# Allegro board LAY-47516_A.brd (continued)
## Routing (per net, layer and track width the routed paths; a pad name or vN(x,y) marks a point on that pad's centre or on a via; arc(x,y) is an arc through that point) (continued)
VCC_2V0: length 7.6
  TOP w0.254: 22.35,73.59 TP13.1 ; TP13.1 21.9,74.04 ; TP13.1 22.8,74.04 ; TP13.1 22.35,74.49 ; 17.59,74.81 C12.1 ; C12.1 18.03,74.39 ; C12.1 18.48,74.81 ; U4.2 17.27,73.78
  BOTTOM w0.254: JP1.3 16.08,60.62 ; JP1.3 17.03,59.66 ; JP1.3 15.12,59.66 ; JP1.3 16.08,58.71
  vias: v2(17.53,72.52) v2(18.67,73.53) v2(18.67,72.52) v2(19.81,75.56) v2(19.81,74.55) v2(19.81,73.53) v2(19.81,72.52) v2(20.95,75.56) v2(20.95,74.55) v2(20.95,73.53) v2(20.95,72.52) v2(22.1,75.56)
VCC_3V3: length 39.7
  TOP w0.254: C27.1 99.44,70.28 99.05,69.89 U12.14 ; C27.1 100.17,71.79 v2(100.2,71.75) ; C27.1 98.46,71.79 C28.1 ; U11.2 v2(24.46,23.06) ; U11.1 v2(23.49,22.3) ; R20.1 v2(25.81,19.8)
  TOP w0.381: 22.35,68.64 TP12.1 ; TP12.1 22.8,69.09 ; TP12.1 22.35,69.54 ; TP12.1 21.9,69.09 ; 17.43,67.61 C7.1 17.01,68.11 ; 17.06,68.68 U3.4 17.7,69.1 ; U3.5 17.7,70.05
  TOP w0.508: R158.1 27.49,36.95 v2(27.3,36.95) ; R153.1 v2(77.14,22.66) ; C22.1 v2(24.46,22.28) ; R152.1 v2(13.97,27.99) ; R37.1 v2(92.09,83.95) 93.12,84.97 93.12,86.31 93.95,87.14 D4.2
  L3_PWR_1 w0.254: JP1.1 17.03,64.74 ; JP1.1 16.08,63.79 ; JP1.1 15.12,64.74 ; JP1.1 16.08,65.7
  BOTTOM w0.508: v2(27.3,36.95) 27.07,36.71 27.07,26.89 v2(26.44,26.26) ; v2(24.46,23.06) v2(24.46,22.28)
  vias: v2(18.52,70.48) v2(18.54,68.96) v2(18.54,67.44) v2(19.69,69.34) v2(19.81,70.48) v2(19.81,67.44) v2(20.45,68.33) v2(21.08,70.48) v2(21.08,69.34) v2(21.08,67.44) v2(22.35,70.48) v2(22.35,67.44)
VCC_3V3_2V0: length 83.1
  TOP w0.165: R62.1 v2(41.24,40.64) ; R34.1 v2(102.11,58.84) ; R149.1 v2(18.26,49.91) ; R148.1 v2(14.91,49.91) ; R35.1 v2(103,58.84)
  TOP w0.254: v2(101.76,72.77) R33.1 R32.1 ; U18.14 44.57,77.52 44.67,77.62 45.35,77.62 v2(45.88,77.09) ; U12.1 96.47,68.31 95.63,69.15 C29.1 v2(96.39,71.75) ; v2(25.71,49.57) 25.52,49.38 U22.16 ; U11.16 22.99,22.61 22.83,22.45 C24.1 ; 17.4,84.59 C466.1 v1(18.29,82.95) ; C97.1 19.88,13.46 19.74,13.59 U24.16 ; U26.1 C444.1 40.92,97.17 40.78,97.03 v2(40.77,97.03)
  TOP w0.381: C8.1 JS1.1
  TOP w0.508: v2(49.34,96.54) R19.1 ; v2(40.78,92.09) C442.1 U25.1 ; D9.A v2(45.52,86.33) ; v2(10.29,7.75) 10.67,8.13 C95.1 11.56,6.57 11.52,6.54 J18.11 ; C84.1 v2(45.88,77.09) ; C58.1 v2(80.64,45.31) ; R44.1 v2(95.48,35.24) ; R61.2 v2(81.66,45.31) ; R117.2 v2(39.34,76.2) ; v2(23.62,21.08) 23.22,21.49 C24.1 ; C59.1 37.91,35.43 37.78,35.56 J10.11 ; R43.1 v2(95.48,13.08) ; v2(46.61,46.86) 47.65,46.86 ; C93.1 26.07,49.93 v2(25.71,49.57) ; C97.1 v2(21.84,13.46) ; R147.1 v2(95.48,46.35) ; R45.1 v2(95.35,24.2) ; R42.2 v2(95.27,89.41)
  L3_PWR_1 w0.254: 35.58,35.56 J10.11 ; J10.11 37.62,35.56 ; J10.11 36.6,36.58 ; 15.12,62.2 JP1.2 ; JP1.2 16.08,61.25 ; JP1.2 17.03,62.2 ; 10.51,5.33 J18.11 ; J18.11 12.54,5.33 ; J18.11 11.52,4.31 ; J18.11 11.52,6.35 ; JP21.1 42.1,55.37 ; JP21.1 41.15,54.42 ; JP21.1 41.15,56.33 ; JP21.1 40.19,55.37 ; 21.97,60.77 JS1.1 21.02,61.72 ; JP20.1 82.74,57.53 ; JP20.1 81.79,58.49 ; JP20.1 80.83,57.53 ; JP20.1 81.79,56.58 ; J18.12 11.52,3.81 ; J18.12 12.54,2.79 ; J18.12 10.51,2.79 ; J18.12 11.52,1.77 ; JP22.1 93.44,34.54 ; JP22.1 92.48,33.59 ; JP22.1 92.48,35.5 ; JP22.1 91.53,34.54 ; JP8.1 41.39,87.33 ; JP8.1 40.44,88.28 ; JP8.1 39.48,87.33 ; JP8.1 40.44,86.37
  BOTTOM w0.165: v1(56.9,31.37) 56.87,31.4 R75.1 ; v1(49.53,49.78) 49.16,49.41 R65.1
VCC_IF_LINK: length 37.6
  TOP w0.254: v2(32,77.6) 30.71,77.6 30.2,77.09 C91.1 29.54,75.34 U21.6 ; U20.6 29.36,82.17 C87.1 30.12,83.57 30.63,84.07 v2(31.24,84.07) ; U17.8 38.75,64.65 38.73,64.64 C83.1 37.46,65.28 37,65.74 v2(36.58,65.74) ; U19.6 29.76,87.67 C86.1 30.18,88.65 30.68,89.15 v2(32,89.15)
  TOP w0.508: C89.1 51.21,73.88 J17.1 ; R122.1 v2(31.99,80.59) ; R126.1 v2(32.04,73.6) ; R116.1 v2(32.03,86.03)
  L3_PWR_1 w0.203: J17.1 50.29,73.02 v2(39.12,73.02)
  BOTTOM w0.254: JP8.2 40.44,85.74 ; JP8.2 41.39,84.79 ; JP8.2 39.48,84.79 ; JP8.2 40.44,83.83
ACC_FC0_I2C_SCL: length 64.9
  TOP w0.165: U12.4 88.32,66.81 86.64,65.13 49.66,65.13 v1(46.63,62.1) ; R77.2 v1(46.63,50.67)
  BOTTOM w0.165: v1(46.63,50.67) v1(46.63,62.1)
ACC_FC0_I2C_SDA: length 72.2
  TOP w0.165: v1(57.25,64.64) 97.41,64.64 98.05,65.29 U12.6
  BOTTOM w0.165: R84.2 57.15,35.44 57.15,50.8 58.17,51.82 58.17,54.86 57.25,55.78 v1(57.25,64.64)
ACC_INT_EXP_P1_23: length 115.5
  TOP w0.165: v1(73.15,74.17) 73.28,74.04 99.06,74.04 99.19,74.17 99.69,74.17 99.95,73.91 99.95,73.74 101.22,72.47 101.22,72.01 101.47,71.75 R36.1 ; v1(73.15,48.51) 86.13,48.51 J9.5 ; v1(73.15,28.83) v1(62.48,28.83) ; v1(62.48,39.24) 61.19,40.54 J32.27
  BOTTOM w0.165: v1(73.15,74.17) v1(73.15,48.51) v1(73.15,28.83) ; v1(62.48,39.24) v1(62.48,28.83)
ARD_ADC0_0_P: length 133.5
  TOP w0.14: J12.10 81.03,15.24 80.64,14.86 76.83,14.86 76.2,15.49 71.37,15.49 71.12,15.24 v1(65.28,15.24) ; v1(50.29,46.73) 50.54,46.48 52.83,46.48 53.19,46.13 U28.12 J32.12 ; v1(47.27,20.4) 47.02,20.14 47.02,18.31 46.61,17.91 42.67,17.91 41.66,18.92 37.74,18.92 J13.3 ; JP4.3 30.35,12.7 J13.8 35.31,11.45 35.31,6.35 37.46,4.19 v1(65.28,4.19)
  BOTTOM w0.14: JP4.3 32.13,11.68 32.38,11.43 34.67,11.43 35.31,12.07 35.31,15.49 36.6,16.79 J13.3 ; v1(65.28,4.19) v1(65.28,15.24) ; v1(50.29,46.73) 48.8,46.73 46.75,44.68 46.75,20.91 v1(47.27,20.4)
ARD_BTN_USR_P1_9: length 177.8
  TOP w0.165: v1(38.73,2.54) 39.88,1.4 85.47,1.4 86.11,2.03 86.11,2.79 87,3.68 88.52,3.68 90.93,1.27 v1(94.49,1.27) ; v1(96.27,51.18) 80.01,51.18 78.87,52.32 64.39,52.32 62.69,50.63 J32.3 ; R47.2 v1(96.27,21.08)
  BOTTOM w0.165: v1(38.73,2.54) 38.73,20.6 37.49,21.84 35.58,21.84 J13.2 ; v1(94.49,1.27) 94.87,1.65 94.87,17.4 96.27,18.8 v1(96.27,21.08) 96.52,21.34 96.52,50.93 v1(96.27,51.18)
ARD_CMP0_IN_A: length 144.6
  TOP w0.165: v1(77.47,58.93) 83.26,58.93 87.4,54.79 J9.1 ; v1(78.49,4.32) 66.17,4.32 65.79,4.7 44.6,4.7 J13.7 ; J32.36 U28.36 v1(78.11,45.63) ; J11.2 91.06,14.48 88.01,11.43 86.87,11.43 86.11,12.19 86.11,13.46 85.6,13.97 78.6,13.97 v1(78.49,14.08)
  BOTTOM w0.165: v1(77.47,58.93) 77.47,46.26 v1(78.11,45.63) 78.16,45.58 78.16,14.41 v1(78.49,14.08) v1(78.49,4.32)
ARD_INT_P0_15: length 64.3
  TOP w0.165: v1(54.99,13.97) 70.31,13.97 71.45,15.11 76.15,15.11 78.56,12.7 J12.12 ; v1(54.86,43.43) 55.46,43.43 55.63,43.6 55.63,44.83 55.33,45.13 J32.14
  BOTTOM w0.165: v1(54.99,13.97) 54.99,43.31 v1(54.86,43.43)
ARD_LEDB_PWM: length 119.6
  TOP w0.165: v1(62.69,61.72) 96.24,61.72 v1(96.75,61.21) ; J32.51 U28.51 v1(62.69,55.75) ; v1(98.88,74.55) 98.12,74.55 97.87,74.8 R161.1 ; J12.8 86.13,16.51 88.77,16.51 90.55,18.29 95.12,18.29 95.89,17.53 v1(99.44,17.53)
  BOTTOM w0.165: v1(98.88,74.55) 98.88,71.86 96.75,69.73 v1(96.75,61.21) 96.75,55.88 99.44,53.19 v1(99.44,17.53) ; v1(62.69,55.75) v1(62.69,61.72)
ARD_LEDG_PWM: length 106.7
  TOP w0.165: v1(98.51,81.97) 98.5,81.96 R162.1 ; J12.4 86.13,21.59 93.98,21.59 94.56,22.17 v1(94.56,24) ; v1(91.92,43.56) 79.88,43.56 79.5,43.94 79.5,46.1 78.97,46.63 U28.38 J32.38
  BOTTOM w0.165: v1(98.51,81.97) 93.75,81.97 91.92,80.14 v1(91.92,43.56) 91.92,41.83 94.74,39.01 94.74,25.27 94.56,25.1 v1(94.56,24)
ARD_LEDR_PWM: length 122
  TOP w0.165: J9.2 83.57,52.32 83.06,52.83 67.06,52.83 65.02,54.86 64.01,54.86 63.69,54.55 U28.49 J32.49 ; v1(94.11,20.32) J12.5 ; J9.13 v1(94.11,37.08) ; v1(88.54,88.65) R164.1
  BOTTOM w0.165: v1(88.54,88.65) 83.82,83.92 83.82,53.34 84.84,52.32 J9.2 84.86,54.76 85.85,55.75 90.68,55.75 91.44,54.99 91.44,41.5 94.11,38.84 v1(94.11,37.08) v1(94.11,20.32)
ARD_MIK_ADC0_8_N: length 108.5
  TOP w0.14: J7.1 62.85,6.39 61.65,5.18 48.03,5.18 47.09,6.12 v1(47.09,10.54) ; J32.7 U28.7 51.42,48.63 50.55,47.75 v1(50.29,47.75) ; v1(47.09,17.2) 46.53,16.64 35.99,16.64 35.48,17.14 35.48,19.2 J13.1 37.62,19.3 37.62,19.3 37.72,19.2 41.77,19.2 42.79,18.19 46.49,18.19 46.74,18.43 46.74,20.18 v1(46.47,20.45)
  BOTTOM w0.14: J13.1 35.34,19.06 33.15,19.06 30.86,16.76 JP4.1 ; v1(50.29,47.75) 49.55,47.01 48.69,47.01 46.45,44.77 46.45,44.7 46.47,44.67 v1(46.47,20.45) ; v1(47.09,10.54) v1(47.09,17.2)
ARD_MIK_FC0_I2C_SCL: length 34.6
  TOP w0.165: v1(45.72,48.77) 45.75,48.79 R80.2
  BOTTOM w0.165: v1(45.72,48.77) 45.72,20.12 J8.5
ARD_MIK_FC0_I2C_SDA: length 21.4
  TOP w0.165: J8.6 56.99,19.09 v1(57.02,19.05)
  BOTTOM w0.165: v1(57.02,19.05) 56.77,19.3 56.77,30.23 57.73,31.19 R88.2
ARD_MIK_FC1_USART_RXD: length 102.7
  TOP w0.165: v1(61.34,37.46) 60.19,38.62 J32.25 ; v1(64.26,5.59) 70.48,5.59 71.02,5.05 75.21,5.05 77.77,7.62 J12.16 ; v1(64.26,12.04) v1(61.34,12.04) 57.51,12.04 56.93,11.47 J8.3 ; J13.4 35.48,16.36 46.91,16.36 48.33,17.77 61.33,17.77 v1(61.34,17.78)
  BOTTOM w0.165: v1(61.34,12.04) v1(61.34,17.78) v1(61.34,37.46) ; v1(64.26,12.04) v1(64.26,5.59)
ARD_MIK_FC1_USART_TXD: length 94.5
  TOP w0.165: J32.62 57.19,52.28 v1(57.53,51.94) ; J12.14 70.36,10.16 67.82,12.7 v1(56.52,12.7) 50.6,12.7 J8.4 35.3,14.01 J13.6
  BOTTOM w0.165: v1(57.53,51.94) 57.53,51.82 56.64,50.93 56.64,35.81 56.26,35.43 56.26,18.92 56.52,18.67 v1(56.52,12.7)
ARD_MIK_HSSPI_MISO: length 105.9
  TOP w0.165: J9.12 80.39,39.62 v1(80.14,39.88) ; v1(80.44,15.34) 77.27,15.34 76.06,16.55 J7.5
  BOTTOM w0.165: JP25.1 72.64,97.25 78.23,91.66 78.23,47.37 80.14,45.47 v1(80.14,39.88) 80.44,39.57 v1(80.44,15.34)
ARD_MIK_HSSPI_MOSI: length 123.7
  TOP w0.165: v1(20.83,19.69) 22.48,19.69 23.11,19.05 29.34,19.05 34.1,23.81 40.57,23.81 43.69,26.92 50.67,26.92 52.7,24.89 v2(70.48,24.89) ; v1(71.63,37.08) J9.14 ; U24.11 16.52,11.57 16.38,11.43 v1(16.38,10.67) ; v1(70.48,19.09) J7.6 ; R138.1 v1(21.69,9.96) ; J32.40 U28.40 v1(71.63,47.63)
  BOTTOM w0.165: v1(71.63,47.63) v1(71.63,37.08) 71.63,26.67 70.48,25.53 v2(70.48,24.89) v1(70.48,19.09) ; v1(21.69,9.96) 21.15,10.5 20.28,10.5 19.81,10.03 18.54,10.03 17.91,10.67 v1(16.38,10.67) 16.38,12.83 19.81,16.26 19.81,18.67 v1(20.83,19.69)
ARD_MIK_HSSPI_SCK: length 105.8
  TOP w0.165: v1(76.71,42.16) J9.10 ; v1(76.07,14.01) J7.4
  BOTTOM w0.165: v1(76.07,14.01) 76.07,22.48 76.71,23.11 v1(76.71,42.16) 76.71,89.59 69.34,96.96 JP26.1
ARD_MIK_HSSPI_SSEL1: length 125.8
  TOP w0.165: v1(70.87,34.54) J9.16 ; U24.14 18.02,12.03 18.75,11.3 v1(21.72,11.3) ; J7.3 v1(69.85,11.47) ; v1(21.97,17.78) 29.72,17.78 34.67,22.73 41.02,22.73 44.13,25.85 50.23,25.85 52.83,23.24 v2(69.85,23.24) ; v1(70.87,47.12) 70.85,47.13 U28.39 J32.39 ; v1(24.26,10.03) R139.1
  BOTTOM w0.165: v1(21.97,17.78) 21.21,17.02 21.21,11.81 v1(21.72,11.3) 21.72,10.92 22.61,10.03 v1(24.26,10.03) ; v1(70.87,47.12) v1(70.87,34.54) 70.87,26.92 69.85,25.91 v2(69.85,23.24) v1(69.85,11.47)
ARD_MIK_P1_5: length 75.3
  TOP w0.165: J32.22 U28.22 v1(58.69,40.64) ; v1(59.82,6.39) J8.1
  BOTTOM w0.165: v1(58.69,40.64) 58.69,36.05 59.82,34.92 v1(59.82,6.39) 59.82,3.43 60.58,2.67 84.73,2.67 J12.20
BRG_I2C0_SCL: length 19.5
  TOP w0.102: U16.D6 v1(11.84,38.17)
  TOP w0.165: R91.2 v1(10.62,43.31)
  BOTTOM w0.165: JS4.1 11.43,53.26 11.43,46.35 11.3,46.23 11.3,45.47 10.62,44.78 v1(10.62,43.31) 11.84,42.09 v1(11.84,38.17)
BRG_I2C0_SDA: length 20.3
  TOP w0.102: U16.E6 v1(12.64,38.17)
  TOP w0.165: R92.2 v1(11.84,43.31)
  BOTTOM w0.165: JS5.1 14.55,53.04 14.55,52.45 12.19,50.09 12.19,46.35 12.32,46.23 12.32,45.34 11.84,44.86 v1(11.84,43.31) 12.19,42.95 12.19,38.61 v1(12.64,38.17)
BRG_INTR_ISP: length 15.6
  TOP w0.102: U16.J5 16.65,36.55 17.3,36.55
  TOP w0.165: 17.3,36.55 18.01,36.55 18.53,37.07 v1(21.97,37.07) ; R132.2 v1(20.88,45.11)
  BOTTOM w0.165: v1(20.88,45.11) 22.1,43.89 22.1,37.2 v1(21.97,37.07)
BRG_INTR_ISP_DIR: length 12.9
  TOP w0.102: 17.26,38.98 16.65,38.98 U16.J7
  TOP w0.165: 17.26,38.98 18.54,40.26 18.54,41.66 20.29,43.41 v1(21.57,43.41) R134.1 U22.7
BRG_ISP_CTRL: length 20.8
  TOP w0.102: U16.A9 v1(8.57,40.17)
  TOP w0.165: v1(18.29,38.76) 19.25,38.76 19.35,38.66 23.31,38.66 24.53,39.88 25.22,39.88 25.46,39.64 U23.2
  BOTTOM w0.165: v1(18.29,38.76) 17.17,37.64 11.1,37.64 v1(8.57,40.17)
BRG_RESET_TXEN: length 48.9
  TOP w0.102: 15.04,41.2 15.04,40.57 U16.G9
  TOP w0.165: R128.1 29.42,74.64 v1(29.4,74.66) 29.37,74.69 U21.5 ; 15.04,41.2 15.04,43.87 v1(17.51,46.34)
  BOTTOM w0.165: v1(17.51,46.34) 17.51,47.73 20.95,51.18 28.7,51.18 31.24,53.72 31.24,57.66 28.7,60.2 28.7,73.96 v1(29.4,74.66)
BRG_SPI1_MISO: length 22.6
  TOP w0.165: U16.J1 17.62,32.38 18.54,32.38 20.7,30.23 20.7,27.94 18.13,25.37 18.13,18.64 17.02,17.53 U24.5
BRG_SPI1_MOSI: length 23.8
  TOP w0.102: U16.J2 15.84,34.17 15.84,33.31
  TOP w0.165: U24.6 16.52,15.66 16.49,15.69 16.49,17.63 17.83,18.97 17.83,25.22 17.78,25.27 17.78,25.53 20.32,28.07 20.32,29.97 18.29,32 17.14,32 15.84,33.31
BRG_SPI1_SCLK: length 33.5
  TOP w0.165: U24.4 17.52,15.66 17.53,15.66 17.53,16.64 v1(17.78,16.89) ; v1(18.36,42.98) 17.58,42.2 17.58,40.72 U16.K9
  BOTTOM w0.165: v1(18.36,42.98) 19.84,41.5 19.84,35.99 20.57,35.26 20.57,27.05 17.78,24.26 v1(17.78,16.89)
BRG_SPI1_SSEL: length 35
  TOP w0.165: U16.K10 17.04,42.56 v1(18.57,44.09) ; U24.3 18.02,15.99 v1(18.41,16.38)
  BOTTOM w0.165: v1(18.41,16.38) 18.92,16.89 18.92,24.89 20.95,26.92 20.95,35.48 20.27,36.17 20.27,42.39 v1(18.57,44.09)
BRG_TCK_SWCLK: length 38.9
  TOP w0.165: v1(38.93,52.26) 38.61,51.94 22.4,51.94 18.52,48.06 18.52,46.61 15.88,43.97 15.88,41.41 U16.H10 ; U17.2 v1(39.68,59.41)
  BOTTOM w0.165: v1(39.68,59.41) 38.93,58.66 v1(38.93,52.26)
BRG_TDI: length 39.1
  TOP w0.165: U17.3 v1(40.33,58.97) ; U16.J10 16.24,43.74 18.93,46.44 18.93,47.89 22.61,51.56 v1(39.37,51.56)
  BOTTOM w0.165: v1(40.33,58.97) 39.37,58.01 v1(39.37,51.56)
BRG_TDO_SWO: length 60.7
  TOP w0.102: 17.27,39.78 16.64,39.78 U16.J8
  TOP w0.165: 17.27,39.78 17.91,40.41 17.91,41.66 19.41,43.15 19.41,47.6 v1(21.17,49.36) ; U19.3 27.01,86.37 27.52,85.86 27.52,72.81 28.87,71.46 v1(29.21,71.46)
  BOTTOM w0.165: v1(21.17,49.36) 21.17,50.41 21.49,50.72 28.88,50.72 31.62,53.47 31.62,57.91 29.21,60.32 v1(29.21,71.46)
BRG_TMS_SWDIO: length 62.5
  TOP w0.165: U16.K4 18.26,36.17 18.72,36.63 23.32,36.63 24.67,37.97 27.18,37.97 27.89,38.68 v1(29.46,38.68) ; U20.3 26.42,79.02 27.18,78.26 27.18,72.52 28.91,70.78 31.45,70.78 v1(31.62,70.61)
  BOTTOM w0.165: v1(29.46,38.68) 29.46,39.24 32.13,41.91 32.13,50.55 34.42,52.83 34.42,65.28 31.62,68.07 v1(31.62,70.61)
BRG_TMS_SWDIO_TXEN: length 66.8
  TOP w0.102: U16.J4 16.64,35.76 18.36,35.76
  TOP w0.165: v1(32.73,70.88) 31.67,71.94 29.02,71.94 27.89,73.08 27.89,81.37 28.03,81.52 U20.5 29.62,81.52 29.64,81.55 R124.1 ; 18.36,35.76 18.92,36.32 23.49,36.32 24.77,37.59 27.3,37.59 27.94,38.23 29.84,38.23 v1(30.23,38.61)
  BOTTOM w0.165: v1(32.73,70.88) 32.73,68.49 34.92,66.29 34.92,52.58 32.51,50.16 32.51,41.27 30.28,39.04 30.28,38.66 v1(30.23,38.61)
BRG_TRST_SWDRST: length 40.2
  TOP w0.165: U21.3 25.02,74.04 v1(22.48,71.5) ; U16.D10 12.24,41.93 v1(12.8,42.49)
  BOTTOM w0.165: v1(22.48,71.5) 22.99,70.99 22.99,56.39 13.82,47.22 13.82,45.59 12.8,44.58 v1(12.8,42.49)
BRG_UART0_RXD: length 13.3
  TOP w0.165: U22.3 v1(23.18,47.66) ; v1(14.45,41.83) 14.64,41.65 U16.G10
  BOTTOM w0.165: v1(23.18,47.66) 23.18,47 22.78,46.61 20.42,46.61 15.65,41.83 v1(14.45,41.83)
BRG_UART0_TXD: length 17.5
  TOP w0.102: U16.G7 v1(14.23,38.97)
  TOP w0.165: U22.4 23.46,47.16 23.45,47.17 v1(22.63,47.17) R129.2
  BOTTOM w0.165: v1(14.23,38.97) 13.67,38.97 13.44,39.2 13.44,41.5 14.35,42.42 15.54,42.42 20.29,47.17 v1(22.63,47.17)
CAN__HSSPI_ISP_PIO1_2: length 150.2
  TOP w0.165: U24.13 v1(17.52,11.75) 17.52,10.84 16.61,9.93 R143.1 ; v2(65.66,23.79) 52.79,23.79 50.38,26.21 43.99,26.21 40.87,23.09 34.52,23.09 29.59,18.16 22.48,18.16 22.23,18.41 v1(21.59,18.41) ; v1(67.69,48.13) U28.41 J32.41 ; JP26.2 70.61,105.66 70.61,90.93 v1(67.56,87.88)
  BOTTOM w0.165: v1(67.56,87.88) 67.56,64.14 65.79,62.36 65.79,53.21 67.69,51.31 v1(67.69,48.13) 67.69,45.59 65.66,43.56 v2(65.66,23.79) ; v1(17.52,11.75) 20.83,15.05 20.83,17.65 v1(21.59,18.41)
CAN__HSSPI_ISP_PIO1_3: length 154
  TOP w0.165: v1(68.33,48.64) 68.31,48.63 U28.42 J32.42 ; JP25.2 71.37,105.66 71.37,90.68 v1(68.07,87.38) ; R140.1 v1(19.15,10.63) ; U24.12 17.02,11.62 17.02,11.62 v1(17.02,11.24) ; v2(66.17,24.38) 52.7,24.38 50.52,26.56 43.84,26.56 40.72,23.45 34.37,23.45 29.46,18.54 22.61,18.54 22.1,19.05 v1(21.21,19.05)
  BOTTOM w0.165: v1(68.07,87.38) 67.95,87.25 67.95,63.75 66.17,61.98 66.17,53.34 68.33,51.18 v1(68.33,48.64) 68.33,45.47 66.17,43.31 v2(66.17,24.38) ; v1(21.21,19.05) 20.32,18.16 20.32,15.24 17.02,11.94 v1(17.02,11.24) 18.55,11.24 v1(19.15,10.63)
CAN_RXD: length 53.3
  TOP w0.165: U25.3 43.11,89.1 43.69,88.52 66.17,88.52 67.56,89.92 67.56,97.03 65.53,99.06 65.53,107.44 66.29,108.2 71.37,108.2 JP25.3
CAN_TXD: length 54.6
  TOP w0.165: JP26.3 68.33,110.49 66.42,110.49 65.02,109.09 65.02,99.06 67.18,96.9 67.18,90.07 66.14,89.03 51.05,89.03 50.06,90.02 50.06,90.7 49.35,91.41 47.04,91.41 46.61,91.84 46.61,93.86 46.04,94.42 43.75,94.42 43.24,94.94 U26.3
CANH: length 31.1
  TOP w0.165: J19.7 44.26,101.19 45.63,99.82 57.75,99.82 D3.1 60.53,95.32 JP23.2 58.55,93.34 U9.7
CANL: length 33.3
  TOP w0.165: J19.2 45.64,100.66 46.1,100.2 58.93,100.2 61.34,97.79 61.66,97.79 D3.2 62.41,96.06 62.1,95.76 61.59,95.76 60.71,94.87 60.71,94.11 59.44,92.84 JP24.2 58.42,92.07 U9.6
EXP_CMP0_IN_B: length 103.3
  TOP w0.165: v1(78.74,46.13) U28.37 J32.37 ; J11.1 91.44,17.02 88.52,14.1 86.61,14.1 86.11,14.61 86.11,15.75 85.34,16.51 80.33,16.51 v1(79.72,17.12) 79.19,17.65 71.63,17.65 70.61,16.64 57.4,16.64 56.13,15.37 36.73,15.37 J13.5
  BOTTOM w0.165: v1(79.72,17.12) 78.74,18.1 v1(78.74,46.13)
EXP_CMP0_OUT: length 124.4
  TOP w0.165: J11.3 91.57,11.94 88.44,8.81 76.99,8.81 75.67,7.49 70.71,7.49 69.19,9.02 v1(55.5,9.02) ; J32.2 v1(55.63,51.13)
  BOTTOM w0.165: v1(55.63,51.13) 55.63,35.81 55.5,35.69 v1(55.5,9.02) ; J11.3 90.37,14.53 90.37,48.31 88.9,49.78 J9.3
EXP_ISP_P1_29: length 133.4
  TOP w0.165: v1(63.37,52.07) 62.03,52.07 61.69,52.41 J32.53 ; v1(40.08,11.05) 47.65,11.05 48.67,10.03 v1(63.75,10.03) 69.01,10.03 71.2,7.85 75.26,7.85 76.68,9.27 v1(82.42,9.27) ; R137.2 v1(25.21,11.94)
  BOTTOM w0.165: v1(63.75,10.03) 63.75,12.19 64.01,12.45 64.01,48.51 63.5,49.02 63.5,51.94 v1(63.37,52.07) ; v1(82.42,9.27) 83.57,9.27 83.82,9.02 85.6,9.02 86.11,9.53 86.11,11.41 J12.11 ; v1(25.21,11.94) 27.05,13.78 27.05,17.91 28.4,19.26 29.93,19.26 33.02,22.35 33.02,24.36 J10.20 36.98,22.48 37.46,22.48 40.08,19.86 v1(40.08,11.05)
FB: length 20.5
  TOP w0.165: C461.1 L11.2 61.76,32.31 61.76,32.31 C18.1 60.56,32.31 60.32,32.54 60.32,33.81 59.92,34.21 C19.1 59.28,37.57 59.69,37.97 U28.24 J32.24 59.69,43.69 60.07,44.07 61.85,44.07 62.19,43.73 J32.29
FC0_I2C_SCL: length 46.8
  TOP w0.165: v1(62.19,61.21) 48.92,61.21 v1(47.65,59.94) ; J32.52 v1(62.19,55.12) ; v1(47.65,51.05) R77.1 R80.1 R74.2 47.14,47.37 40.26,47.37 38.61,45.72 J10.3
  BOTTOM w0.165: v1(62.19,55.12) v1(62.19,61.21) ; v1(47.65,59.94) v1(47.65,51.05)
FC0_I2C_SDA: length 63.6
  TOP w0.165: v1(75.69,50.16) 75.66,50.13 U28.45 J32.45 ; J9.18 77.47,32 v1(75.68,30.22) 75.44,29.97 v1(57.91,29.97)
  BOTTOM w0.165: v1(75.69,50.16) 75.69,30.23 v1(75.68,30.22) ; v1(57.91,29.97) 57.91,30.61 58.29,30.99 58.29,33.02 58.14,33.17 R88.1 R75.2 R84.1
FC0_USART_RXD: length 66.5
  TOP w0.165: J32.61 U28.61 57.69,54.86 57.31,55.24 54.36,55.24 53.59,54.48 45.97,54.48 42.42,50.93 30.35,50.93 29.08,49.66 v1(29.08,49.15) 29.46,49.15 29.67,48.95 R130.2 ; 20.4,22.73 v1(19.43,22.73)
  BOTTOM w0.165: v1(19.43,22.73) 19.43,24.38 21.34,26.29 21.34,35.18 22.48,36.32 22.48,44.2 27.43,49.15 v1(29.08,49.15)
FC0_USART_TXD: length 91.8
  TOP w0.165: v1(21.07,25.34) 20.7,25.71 R26.2 ; v1(42.67,28.58) 42.24,29.01 35.13,29.01 J10.18 ; J32.63 56.69,52.63 56.52,52.45 45.59,52.45 43.56,50.42 v1(42.67,50.42) 31.5,50.42 v1(30.23,49.15) 30.23,47.37 30.02,47.16 R131.2
  BOTTOM w0.165: v1(30.23,49.15) 28.24,47.16 26.34,47.16 22.86,43.69 22.86,36.2 21.84,35.18 21.84,26.12 v1(21.07,25.34) ; v1(42.67,28.58) v1(42.67,50.42)
FC1_I2C_SCL: length 225.7
  TOP w0.165: v1(64.26,64.14) 49.53,64.14 43.74,58.34 40.31,58.34 35.42,53.45 14.16,53.45 JS4.2 R148.2 1.78,49.91 1.75,49.93 v1(1.37,49.93) ; J12.19 85.88,1.02 36.07,1.02 v1(35.05,2.03) ; v1(17.91,9.93) R144.2 17.3,8.54 v1(17.3,6.7) ; J32.47 v1(64.26,51.13)
  BOTTOM w0.165: v1(17.91,9.93) 16.28,9.93 12.93,6.58 8.79,6.58 6.6,8.76 3.99,8.76 1.37,11.38 v1(1.37,49.93) ; v1(35.05,2.03) 35.05,6.07 J13.11 J13.12 33.14,6.7 v1(17.3,6.7) ; v1(64.26,51.13) v1(64.26,64.14)
FC1_I2C_SDA: length 165.8
  TOP w0.165: v1(66.93,50.63) U28.46 J32.46 ; v1(15.37,9.93) R145.2 14.59,8.37 v1(14.59,7.27) ; v1(65.41,63.5) 50.55,63.5 44.83,57.78 40.51,57.78 35.69,52.96 19.94,52.96 19.28,52.3 JS5.2 R149.2 15.62,49.17 v1(2.17,49.17)
  BOTTOM w0.165: v1(2.17,49.17) 1.83,48.83 1.83,11.71 4.47,9.07 6.78,9.07 8.71,7.14 12.57,7.14 v1(15.37,9.93) ; v1(65.41,63.5) 65.41,52.15 v1(66.93,50.63) ; J13.9 J13.10 31.18,7.27 v1(14.59,7.27)
FC3_MISO: length 15
  TOP w0.165: U29.2 16.13,96.65 14.86,97.92 JP27.1
FC3_MOSI: length 25.3
  TOP w0.165: JP28.1 4.83,100.2 4.83,88.39 6.22,87 12.83,87 13.59,86.23 U29.5
FC3_SCK: length 12.2
  TOP w0.165: U29.6 14.86,85.47 12.95,87.38 7.87,87.38 6.35,88.9 JP30.1
FC3_SSEL0: length 14.7
  TOP w0.165: JP29.1 10.67,89.79 16.89,89.79 17.4,90.3 17.4,91.94
FL_2V5: length 71.8
  TOP w0.254: U24.7 v2(16.02,16.11) ; 30.5,61.09 U1.2 ; U1.2 33.66,61.09 35.31,59.44 36.58,59.44 C82.1 39.02,60.32 U17.1 39.03,62.78 39.75,63.5 42.93,63.5 43.43,64.01 R113.2 ; U1.2 31.8,60.3 ; 31.12,54.35 C5.1 30.6,54.86 ; C90.1 25.63,75.31 25.66,75.34 U21.1 26.4,75.85 26.37,75.88 v2(26.37,76.45) ; R129.1 21.09,48.27 21.52,48.7 v2(22.85,48.7) 23.38,48.16 U22.2 ; 30.73,55.88 C4.1 31.15,56.38 ; U16.F10 v2(13.84,43.3) ; v2(23.37,42.22) C94.1 U23.5 ; U24.2 v2(19.39,15.06) 19.39,14.69 18.99,14.29 U24.1 20.06,14.09 C96.1 ; U20.1 25.43,82.17 25.43,82.18 C88.1 v2(23.99,82.18) ; v2(24.79,49.53) 25.02,49.31 U22.1 ; 23.88,55.05 TP11.1 ; TP11.1 23.88,55.95 ; TP11.1 23.43,55.5 ; TP11.1 24.32,55.5 ; v2(24.2,87.67) C85.1 25.58,87.67 U19.1 ; U24.15 v2(19.3,12.62)
  TOP w0.381: U16.B2 v1(10.24,34.17) ; v2(18.31,37.54) 17.74,36.97 U16.K5 ; U16.C5 v1(11.04,36.57)
  TOP w0.508: C72.1 v2(8.1,33.58) ; C70.1 18.52,37.74 v2(18.31,37.54) ; v2(24.79,49.53) 24.44,49.89 C92.1 ; R91.1 v2(10.62,45.97) ; C69.1 v2(8.15,36.96) ; L10.1 v2(23.41,35.71) 24.74,34.39 R105.1 ; R92.1 v2(11.84,45.97) ; v2(13.84,43.3) 14.33,43.79 C71.1 ; R100.1 v2(5.11,39.98) ; R98.1 5.13,38.94 v2(5.11,38.91) ; R97.1 v2(5.11,36.07) ; J16.1 3.76,17.42 3.73,17.4 2.41,17.4 v2(2.41,18.31) ; R151.1 v2(15.21,27.97) ; R96.1 v2(5.11,37.85)
  L3_PWR_1 w0.254: 11.71,11.85 JP9.1 ; JP9.1 12.66,12.8 ; JP9.1 11.71,13.76 ; JP9.1 10.75,12.8 ; 4.65,18.13 J16.1 3.95,17.42
  vias: v2(19.3,56.13) v2(19.3,54.99) v2(20.45,56.13) v2(25.91,55.12) v2(26.8,56.26) v2(26.8,55.12) v2(26.8,54.1) v2(27.94,57.28) v2(27.94,56.26) v2(27.94,55.12) v2(27.94,54.1) v2(29.08,57.28) v2(29.08,56.26) v2(29.08,55.12) v2(29.08,54.1) v2(30.23,57.28) v2(30.23,56.26) v2(30.23,55.12) v2(30.23,54.1)
FL_BOOT0_LED: length 10.4
  TOP w0.165: U16.K2 18.45,33.16 18.68,33.16 20.23,31.61 23.84,31.61 R105.2 R106.1
FL_BOOT1: length 4.9
  TOP w0.165: U16.K1 v1(17.96,32.85) 18.5,32.85 20.31,31.04 R99.2
FL_BOOT2: length 5.6
  TOP w0.102: U16.C6 11.02,38.18 11.02,38.33 11.02,38.33 11.02,38.78 10.85,38.96 9.37,38.96
  TOP w0.165: R100.2 8.03,39.98 9.04,38.96 9.37,38.96
FL_BOOT3: length 3.8
  TOP w0.165: U16.B10 10.37,41.24 10.37,41.51 v1(9.57,42.3) 8.92,42.96 R101.2
FL_ISP_BOOT: length 15.4
  TOP w0.165: v1(9.78,45.89) 9.78,43.23 11.44,41.57 U16.C10
  BOTTOM w0.165: JP6.1 10.67,53.64 10.67,47.83 9.78,46.94 v1(9.78,45.89)
FL_JTAG_CLK_SWD_CLK: length 30.4
  TOP w0.102: U16.H2 15.04,34.17 15.04,33.35
  TOP w0.165: 15.04,33.35 17.02,31.37 17.65,31.37 18.03,30.99 v1(18.41,30.99) 18.54,30.99 19.66,29.87 R102.1
  BOTTOM w0.165: J16.4 9.5,19.74 14.27,19.74 15.24,20.7 15.24,24.13 18.41,27.3 v1(18.41,30.99)
FL_JTAG_TDI: length 34.5
  TOP w0.102: U16.G3 v1(15.03,34.97)
  BOTTOM w0.165: J16.8 11.23,18.92 14.48,18.92 16,20.45 16,23.19 19.3,26.49 19.3,31.37 18.54,32.13 17.91,32.13 17.27,32.77 17.27,35.1 16.05,36.32 15.49,36.32 15.03,35.86 v1(15.03,34.97)
FL_JTAG_TDO_SWD_SWO: length 30.3
  TOP w0.102: U16.H3 v1(15.83,34.97)
  BOTTOM w0.165: v1(15.83,34.97) 15.83,34.59 15.82,34.58 15.82,33.4 17.73,31.5 18.76,31.5 18.92,31.33 18.92,27.3 15.62,24 15.62,20.57 14.48,19.43 14.4,19.35 10.39,19.35 J16.6
FL_JTAG_TMS_SWD_IO: length 29.9
  TOP w0.102: U16.C4 11.02,35.76 11.02,35.61 11.02,35.61 11.02,35.15 10.85,34.98 9.58,34.98
  TOP w0.165: J16.2 5.92,18.69 5.33,19.28 2.11,19.28 1.3,20.09 1.3,30.81 5.03,34.54 8.13,34.54 8.56,34.98 9.58,34.98
FL_JTAG_TRST: length 3.9
  TOP w0.102: U16.B4 10.23,35.76 9.6,35.76
  TOP w0.165: 9.6,35.76 9.27,35.43 v1(8.07,35.43) 7.82,35.18 R104.2
FL_RST#: length 39.6
  TOP w0.102: U16.B6 10.24,38.17 9.59,38.17
  TOP w0.165: 9.59,38.17 9.4,38.35 8.51,38.35 7.92,38.94 R98.2 6.58,38.4 4.8,38.4 0.66,34.26 0.66,13.97 3.48,11.15 4.72,11.15 J16.10
FL_USB0_DM: length 50.8
  TOP w0.102: 12.62,32.85 12.62,34.15 U16.E2
  TOP w0.14: v1(12.95,31.04) 13.21,31.29 13.21,32.26 12.62,32.85 ; R1.2 11.28,62.1 12.2,62.1 v1(12.53,62.44)
  BOTTOM w0.14: v1(12.53,62.44) 12.2,62.1 10.92,62.1 8.79,59.97 8.77,59.97 3.28,54.47 3.28,33.41 4.46,32.23 12.68,32.23 13.15,31.76 13.15,31.26 v1(12.95,31.04)
FL_USB0_DP: length 49.4
  TOP w0.14: U16.E1 13.04,32.83 13.49,32.37 13.49,31.34 v1(13.75,31.08) ; R2.2 11.3,61.82 12.17,61.82 v1(12.53,61.47)
  BOTTOM w0.14: v1(12.53,61.47) 12.17,61.82 11.04,61.82 8.9,59.69 8.89,59.69 3.56,54.36 3.56,33.53 4.57,32.51 12.83,32.51 13.46,31.88 13.46,31.37 v1(13.75,31.08)
FL_USB0_ID: length 49.3
  TOP w0.165: R3.2 v1(12.61,59.31) ; R93.2 v1(17.35,27.69)
  BOTTOM w0.165: v1(17.35,27.69) 17.35,29.39 13.11,33.63 9.3,33.63 8.74,34.19 5.08,34.19 3.84,35.43 3.84,54.13 9.02,59.31 v1(12.61,59.31)
FL_USB_5V0: length 64.5
  TOP w0.254: TP14.1 14.23,66.17 ; TP14.1 13.59,66.81 ; TP14.1 13.59,65.53 ; TP14.1 12.95,66.17 ; C2.1 33.97,63.34 ; C2.1 33.97,62.34 ; C2.1 33.55,62.84 ; 33.97,64.42 C3.1 ; C3.1 33.46,64.94 ; C3.1 33.97,65.45 ; L1.2 11.01,65.55 ; L1.2 10.41,65.05 ; L1.2 10.41,66.04 ; L1.2 9.81,65.55 ; 6.35,67.78 D1.A ; D1.A 6.35,69.38 ; D1.A 7.16,68.58 ; D1.A 5.55,68.58 ; 30.5,63.39 U1.3 ; U1.3 31.8,64.18 ; U1.3 33.1,63.39 ; U1.3 31.8,62.6
  TOP w0.508: R94.2 v2(16.28,27.97)
  L3_PWR_1 w0.508: v2(16.28,27.97) 16.79,28.47 24.03,28.47 28.07,32.51 28.07,44.45 35.31,51.69 35.31,62.36 v2(33.78,63.88)
IF_DETECT: length 79.6
  TOP w0.165: R125.1 54.78,79.03 D10.C 53.55,78.99 J17.9 51.18,79.88 50.8,80.26 v1(49.91,80.26) ; R103.1 6.1,45.19 8.56,47.65 17.55,47.65 22.35,52.45 35.81,52.45 40.51,57.15 v1(44.45,57.15)
  BOTTOM w0.165: v1(44.45,57.15) 44.45,67.82 46.48,69.85 46.48,72.9 47.88,74.3 47.88,78.74 49.4,80.26 v1(49.91,80.26)
IF_TCK_SWDCLK: length 33.2
  TOP w0.165: JP13.2 33.93,70.26 34.54,70.87 v1(42.42,70.87) 42.93,70.36 v1(48.89,70.36) ; U18.3 42.3,75.56 v1(42.29,75.56) ; v1(42.42,79.74) D11.5
  BOTTOM w0.165: 49.91,75.18 48.89,74.17 v1(48.89,70.36) ; v1(42.42,79.74) 42.42,76.07 42.29,75.95 v1(42.29,75.56) 42.29,74.93 42.42,74.8 v1(42.42,70.87)
IF_TDI: length 19.9
  TOP w0.165: D11.3 46.48,80.39 v1(47.12,79.76) 49.15,77.72 49.91,77.72
  BOTTOM w0.165: JP14.1 44.86,68.86 45.34,69.34 45.34,73.15 46.86,74.68 46.86,79.5 v1(47.12,79.76)
IF_TDO_SWO: length 31.2
  TOP w0.165: 49.91,76.45 48.51,76.45 48.01,75.95 v1(47.37,75.95) 46.42,75.95 46.42,75.96 U18.11 ; JP15.2 36.02,87.81 36.58,87.25 36.58,81.15 37.34,80.39 D11.4 43.29,80.76 44.07,81.53 v1(46.74,81.53)
  BOTTOM w0.165: v1(46.74,81.53) 47.62,80.64 47.62,79.63 47.37,79.38 v1(47.37,75.95)
IF_TMS_SWDIO: length 34.9
  TOP w0.165: U18.7 44.57,73.28 44.83,73.02 48.77,73.02 49.4,72.39 v1(49.4,72.01) v1(41.4,72.01) ; D11.6 41.43,79.09 v1(41.4,79.12) 41.37,79.09 37.62,79.09 35.01,81.7 JP16.2
  BOTTOM w0.165: 49.91,73.91 49.91,73.41 49.4,72.9 v1(49.4,72.01) ; v1(41.4,79.12) 41.4,75.95 41.78,75.56 41.78,72.39 v1(41.4,72.01)
IF_TRST_SWDRST: length 31.9
  TOP w0.165: v1(44.2,78.74) 44.2,80.52 44.7,81.03 46.48,81.03 48.51,78.99 49.91,78.99 ; v1(44.2,78.74) 44.2,78.61 44.17,78.59 U18.15 ; v1(44.2,78.74) 44.54,79.09 D11.1 ; JP17.2 35.33,75.29 39.12,71.5 43.69,71.5 v2(44.32,70.87)
  BOTTOM w0.165: v1(44.2,78.74) 44.32,78.61 v2(44.32,70.87)
ISP_P1_19: length 84
  TOP w0.165: v1(27.79,9.55) 33.66,3.68 v1(61.85,3.68) ; J32.26 U28.26 60.69,40.15 v1(61.21,39.62) ; R142.2 v1(20.45,9.96)
  BOTTOM w0.165: v1(20.45,9.96) 21.01,9.4 22.35,9.4 22.5,9.55 v1(27.79,9.55) ; v1(61.85,3.68) 61.85,38.99 v1(61.21,39.62)
LPC_VDDA: length 12
  TOP w0.165: J32.9 54.34,47.62 51.05,47.62 50.67,47.24 50.16,47.24 49.66,46.74 49.66,45.59 49.1,45.04 47.57,45.04 47.57,45.03 46.68,45.03 46.67,45.04 C460.1 44.95,45.03 R166.2
LX: length 8.1
  TOP w0.165: J32.31 63.19,38.43 62.97,38.2 L11.1
MCU_VBAT: length 40.5
  TOP w0.165: JP22.2 90.93,32 89.53,33.4 70.48,33.4 69.7,34.19 C459.1 C458.1 C457.1 C467.1 64.67,38.2 63.69,39.18 U28.32 J32.32 63.69,43.5 64.32,44.13 J32.33
MCU_VDD: length 19.8
  TOP w0.165: v1(53.21,43.18) 53.21,43.94 53.4,44.13 U28.16 J32.16 ; v2(52.96,48.13) 53.21,48.13 53.22,48.13 U28.8 J32.8
  TOP w0.254: v1(64.25,49.13) J32.43 ; J32.56 60.19,52.33 v1(60.45,52.07) ; J32.28 v1(61.69,43.57)
  L3_PWR_1 w0.254: JP20.2 79.25,58.49 ; JP20.2 78.29,57.53 ; JP20.2 79.25,56.58 ; JP20.2 80.2,57.53
  BOTTOM w0.165: C451.1 54.73,48.13 v2(52.96,48.13)
  BOTTOM w0.254: v1(64.25,49.13) 64.66,49.13 64.9,48.9 C446.1 ; C447.1 C450.1 61.72,43.54 v1(61.69,43.57) ; C448.1 C449.1 60.63,53.17 60.63,52.25 v1(60.45,52.07)
MCU_VDDA: length 9.9
  TOP w0.165: v1(41.15,45.09) 41.2,45.03 R166.1
  BOTTOM w0.165: JP21.2 v1(41.15,45.09)
MIK_EXP_BTN_WK: length 149.4
  TOP w0.165: J32.44 U28.44 v1(67.06,49.63) ; J10.1 42.42,48.26 v1(43.31,49.15) ; v1(66.29,5.08) 69.01,5.08 69.39,4.7 76.81,4.7 78.56,6.45 86.23,6.45 J12.15 89.03,7.62 91.95,10.54 93.85,10.54 94.61,11.3 R46.2 ; v1(65.79,8.05) 52.55,8.05 51.68,8.93 J8.2
  BOTTOM w0.165: v1(67.06,49.63) 67.06,45.85 65.15,43.94 65.15,16 65.79,15.37 v1(65.79,8.05) 65.79,5.59 v1(66.29,5.08) ; J8.2 45.05,8.93 43.31,10.67 v1(43.31,49.15)
N4M_ISP_MODE: length 155.9
  TOP w0.165: J17.7 D12.C v1(59.31,77.72) ; R133.2 v1(31.5,46.02) 31.5,49.05 32.36,49.91 44.07,49.91 46.23,52.07 56.77,52.07 57.4,51.43 58.55,51.43 59.18,52.07 59.18,53.47 J32.58 U28.58 59.19,55.38 59.31,55.5 v1(59.31,56.26) 64.26,56.26 67.31,53.21 82.93,53.21 84.33,54.61 v1(86.21,54.61) ; J9.7 92.55,44.7 92.67,44.58 R150.2 ; R135.2 v1(27.43,39.5) ; R136.2 v1(22.99,12.78)
  BOTTOM w0.165: v1(86.21,54.61) 86.21,45.9 J9.7 ; v1(31.5,46.02) 31.5,42.16 28.83,39.5 v1(27.43,39.5) 27.43,38.23 26.42,37.21 26.42,30.99 25.27,29.84 25.27,25.15 22.99,22.86 22.99,20.7 23.49,20.19 23.49,19.18 23.06,18.74 23.06,12.85 v1(22.99,12.78) ; v1(59.31,56.26) v1(59.31,77.72)
N4M_RESET#: length 178
  TOP w0.165: J32.23 59.19,43.68 v1(59.18,43.69) ; v1(60.32,10.82) 68.94,10.82 70.83,8.93 J7.2 ; J10.10 J10.9 ; v1(39.14,21.72) 40.64,21.72 41.78,22.86 50.22,22.86 51.54,21.54 v1(60.33,21.54) 64.34,21.54 65.53,22.73 73.53,22.73 74.93,24.13 92.2,24.13 96.39,28.32 R48.2 ; v1(43.69,77.8) 43.77,77.71 U18.16
  BOTTOM w0.165: v1(43.69,77.8) 43.69,70.74 43.05,70.1 41.66,70.1 41.15,69.6 41.15,65.41 38.61,62.86 38.61,52.58 38.48,52.45 38.48,52.07 38.61,51.94 38.61,40.11 J10.9 39.14,35.56 v1(39.14,21.72) ; v1(60.32,10.82) 60.33,10.82 v1(60.33,21.54) 60.32,21.54 60.32,35.05 59.18,36.2 v1(59.18,43.69)
N4M_SWDCLK: length 123.1
  TOP w0.165: v2(37.97,44.07) 39.12,44.07 40.64,45.59 48.01,45.59 49.02,46.61 49.02,47.88 50.8,49.66 v1(52.2,49.66) 52.73,49.13 U28.6 J32.6 ; v1(53.09,26.8) 77.47,26.8 78.87,28.19 86.13,28.19 J9.19 ; U18.4 43.09,75.16 42.36,74.42 R115.1 41.16,74.41 41.16,73.52 42.16,72.52 v1(47.62,72.52)
  BOTTOM w0.165: v1(53.09,26.8) 53.09,40.3 51.82,41.57 51.82,47.37 51.69,47.5 51.69,48.89 51.82,49.02 52.2,49.4 v1(52.2,49.66) 52.2,54.99 53.72,56.52 53.72,66.29 51.18,68.83 48.77,68.83 47.62,69.98 v1(47.62,72.52) ; v2(37.97,44.07) 37.34,44.07 37.08,44.32 36.2,44.32 35.31,43.43 35.31,41.89 J10.8
N4M_SWDIO: length 113.9
  TOP w0.165: v1(50.04,69.34) 50.04,72.39 49.02,73.41 45.34,73.41 44.97,73.77 U18.8 ; J10.6 35.46,44.58 38.92,44.58 40.44,46.1 47.81,46.1 48.39,46.68 48.39,47.95 50.6,50.16 v1(52.7,50.16) 53.24,49.63 U28.5 J32.5 ; v1(53.59,28.32) 77.85,28.32 80.39,30.86 86.26,30.86 J9.17
  BOTTOM w0.165: v1(53.59,28.32) 53.59,29.34 53.47,29.46 53.47,40.64 52.2,41.91 52.2,47.5 52.07,47.62 52.07,48.77 52.7,49.4 v1(52.7,50.16) 52.7,54.86 54.1,56.26 54.1,66.67 51.43,69.34 v1(50.04,69.34)
N4M_SWO: length 98.9
  TOP w0.165: J32.13 U28.13 v1(52.7,45.63) ; J9.20 79.5,29.46 77.5,27.46 54.13,27.46 v1(54.1,27.43) ; v1(48.64,77.22) 47.82,76.39 45.71,76.39 45.68,76.36 U18.12
  BOTTOM w0.165: J9.15 86.11,33.25 86.11,30.71 J9.20 ; v1(48.64,77.22) 48.39,76.96 48.39,70.23 48.77,69.85 51.74,69.85 54.48,67.11 54.48,56.13 53.21,54.86 53.21,49.4 52.45,48.64 52.45,47.75 52.7,47.5 v1(52.7,45.63) 52.7,41.91 53.85,40.77 53.85,29.97 54.1,29.72 v1(54.1,27.43)
P0_7: length 22.7
  TOP w0.165: J32.1 U28.1 46.8,51.63 42.93,47.75 38.99,47.75 38.1,46.86 35.2,46.86 J10.4
P0_8: length 21.9
  TOP w0.165: J32.17 U28.17 56.19,41.2 55.63,40.64 53.85,40.64 52.07,42.42 37.36,42.42 J10.5
P0_19: length 87.6
  TOP w0.165: v1(90.93,19.05) 87.12,19.05 85.85,20.32 J12.6 ; J32.60 U28.60 58.19,59.59 59.18,60.58 85.22,60.58 v1(90.93,54.86) ; v1(90.93,39.62) J9.11
  BOTTOM w0.165: v1(90.93,54.86) v1(90.93,39.62) v1(90.93,19.05)
P0_20: length 66.4
  TOP w0.165: J9.4 79.76,49.78 77.91,51.63 U28.48 J32.48
  BOTTOM w0.165: J9.4 83.69,48.62 83.69,44.07 84.33,43.43 86.13,43.43 J9.9 86,40.77 84.07,40.77 83.31,40 83.31,28.45 84.07,27.69 88.39,27.69 89.41,26.67 89.41,17.25 J12.9
P0_27: length 74.9
  TOP w0.165: v1(54.48,3.17) 55.12,2.54 81.66,2.54 82.8,3.68 86,3.68 J12.17 ; J32.18 U28.18 56.69,40.82 54.99,39.12 v1(54.36,39.12)
  BOTTOM w0.165: v1(54.48,3.17) 54.36,3.3 54.36,26.8 54.61,27.05 54.61,30.1 54.36,30.35 v1(54.36,39.12)
P0_31: length 27.7
  TOP w0.165: J32.15 U28.15 53.01,44.63 51.31,42.93 v1(39.62,42.93) ; J10.2 35.2,49.4 39.24,49.4 v1(39.62,49.02)
  BOTTOM w0.165: v1(39.62,42.93) v1(39.62,49.02)
P1_0: length 63.4
  TOP w0.165: v1(63.5,20.49) 73.49,20.49 75.03,18.95 86.23,18.95 J12.7 ; v1(62.86,50.13) J32.4
  BOTTOM w0.165: v1(63.5,20.49) 63.5,48.26 62.86,48.89 v1(62.86,50.13)
P1_4: length 83.6
  TOP w0.165: J32.64 U28.64 56.19,54.43 55.88,54.74 v1(55.5,54.74) ; J12.18 81.53,5.08 79.63,3.17 v1(56.01,3.17)
  BOTTOM w0.165: v1(56.01,3.17) 55.88,3.3 55.88,8.76 56.01,8.89 56.01,9.14 55.88,9.27 55.88,35.56 56.26,35.94 56.26,51.18 55.5,51.94 v1(55.5,54.74)
P1_21: length 187.5
  TOP w0.165: v1(45.09,67.69) 56.64,67.69 v1(56.77,67.82) ; v1(18.48,89.6) 16.13,87.25 U29.7 ; v1(58.19,39.88) U28.21 J32.21 ; v1(59.31,26.03) 53.09,26.03 50.93,28.19 v1(45.09,28.19) ; J12.13 86.13,11.43 75.69,11.43 74.3,12.83 69.09,12.83 68.71,13.21 v1(59.31,13.21)
  BOTTOM w0.165: v1(58.19,39.88) 58.19,35.41 59.31,34.29 v1(59.31,26.03) v1(59.31,13.21) ; v1(45.09,67.69) v1(45.09,28.19) ; v1(56.77,67.82) 56.77,77.22 50.93,83.06 50.93,86.23 45.59,91.57 20.45,91.57 v1(18.48,89.6)
P1_25: length 150.6
  TOP w0.165: v1(82.8,60.07) 63.25,60.07 v1(63.19,60.02) ; v1(63.19,55.12) J32.50 ; v1(14.86,96.01) U29.3
  BOTTOM w0.165: v1(82.8,60.07) 82.8,28.32 83.95,27.18 88.01,27.18 88.77,26.42 88.77,24.23 J12.3 ; v1(63.19,55.12) v1(63.19,60.02) 63.19,84.76 58.42,89.53 51.05,89.53 44.58,96.01 v1(14.86,96.01)
SPI_FLASH_PIO0_2: length 146.7
  TOP w0.165: v1(60.71,55.75) 61.19,55.27 U28.54 61.19,51.33 v1(61.21,51.31) ; v1(62.99,25.4) J12.2
  BOTTOM w0.165: v1(61.21,51.31) 62.36,50.16 62.36,48.89 63.12,48.13 63.12,26.29 62.99,26.16 v1(62.99,25.4) ; JP27.2 3.81,96.52 4.83,95.5 4.83,93.6 6.1,92.33 8.38,92.33 9.4,93.34 45.34,93.34 50.8,87.88 56.39,87.88 60.71,83.57 v1(60.71,55.75)
SPI_FLASH_PIO0_3: length 158.4
  TOP w0.165: J32.55 U28.55 v1(60.69,54.85) ; v2(61.47,62.74) v2(80.26,62.74)
  BOTTOM w0.165: J12.1 86.13,26.67 83.69,26.67 80.77,29.59 80.77,44.7 81.15,45.09 81.15,45.59 80.26,46.48 v2(80.26,62.74) ; JP28.2 3.81,100.2 5.08,98.93 5.08,97.16 6.86,95.38 44.7,95.38 51.31,88.77 56.26,88.77 61.47,83.57 v2(61.47,62.74) 61.47,55.63 v1(60.69,54.85)
SPI_FLASH_PIO0_4: length 143.8
  TOP w0.165: J10.14 35.36,31.72 37.77,31.72 38.89,30.61 60.71,30.61 v1(60.83,30.48) ; v1(59.69,51.69) J32.57 U28.57 v1(59.69,54.86)
  BOTTOM w0.165: v1(59.69,51.69) 61.85,49.53 61.85,46.1 60.83,45.09 60.83,43.18 60.32,42.67 60.32,39.75 60.83,39.24 v1(60.83,30.48) ; v1(59.69,54.86) 58.8,55.75 58.8,84.58 56.01,87.38 50.8,87.38 45.21,92.96 15.11,92.96 14.1,91.95 5.97,91.95 JP29.2
SPI_FLASH_PIO0_6: length 140.1
  TOP w0.165: v1(58.67,29.29) 58.62,29.34 35.2,29.34 J10.16 ; v1(58.67,52.2) 58.69,52.21 J32.59 U28.59 58.69,54.85 v1(58.67,54.86)
  BOTTOM w0.165: v1(58.67,29.29) 58.67,33.66 57.53,34.8 57.53,50.42 58.67,51.56 v1(58.67,52.2) ; JP30.2 5.08,91.57 19.56,91.57 20.57,92.58 45.09,92.58 50.67,87 50.93,87 51.18,86.74 55.88,86.74 58.29,84.33 58.29,55.24 v1(58.67,54.86)
SWD_SW_SEL: length 62.7
  TOP w0.102: U16.G5 15.03,37.36 17.3,37.36 18.16,38.23
  TOP w0.165: v1(35.43,76.96) 37.08,75.31 R119.2 ; 18.16,38.23 19.43,38.23 19.56,38.35 26.9,38.35 27.66,39.12 29.21,39.12 29.34,39.24 29.59,39.24 29.72,39.12 31.39,39.12 v1(31.5,39.22)
  BOTTOM w0.165: v1(35.43,76.96) 35.43,52.32 32.89,49.78 32.89,40.61 v1(31.5,39.22)
SYS_5V0: length 37.1
  TOP w0.254: U26.6 45.41,97.72 44.83,98.3 C445.1 v2(45.8,98.42)
  TOP w0.381: 14.92,75.98 U4.3 ; U4.3 15.62,75.08 ; U4.3 16.32,75.98 ; U4.3 15.62,76.87 ; D1.C 3.55,69.38 ; D1.C 4.36,68.58 ; D1.C 2.75,68.58 ; D1.C 3.55,67.78 ; 15.61,77.02 C11.1 ; C11.1 15.61,77.92 ; C11.1 16.04,77.47 ; 17.06,71.43 U3.6 17.7,71 ; 13.49,71 U3.1 14.13,71.43 ; 14.13,68.68 U3.3 ; 10.23,72.38 C10.1 ; C10.1 10.74,71.87 ; C10.1 11.25,72.38 ; 12.29,71.07 C6.1 ; C6.1 12.8,71.58 ; C6.1 13.32,71.07
  TOP w0.508: U25.6 45.28,92.51 45.11,92.68 C443.1 v2(46.02,93.34) ; TP6.1 50.29,97.66 v2(49.66,98.3) ; C23.1 v2(50.85,96.14) 50.8,96.09 50.8,93.09 49.78,92.07 U9.3 ; R60.1 v2(41.24,25.4) ; C57.1 J10.13 ; R154.1 v2(41.78,21.63)
  L3_PWR_1 w0.254: 36.6,32 J10.13 ; J10.13 36.6,34.04 ; J10.13 35.58,33.02 ; J10.13 37.62,33.02
  vias: v2(4.95,52.07) v2(5.97,52.07) v2(11.15,71.75) v2(11.15,70.74) v2(11.15,69.72) v2(11.15,68.71) v2(11.91,71.75) v2(11.91,70.74) v2(11.91,69.72) v2(11.91,68.71)
UART_SPI_EN#: length 52.5
  TOP w0.165: U22.9 25.52,44.07 25.78,43.81 25.78,42.67 25.4,42.29 v1(24.51,42.29) ; U24.9 14.6,13.59 12.85,15.34 JP9.2 R146.1 v1(8.99,14.5)
  BOTTOM w0.165: v1(8.99,14.5) R146.1 10.34,16.69 16.31,16.69 17.22,15.77 18.44,15.77 19.3,16.64 19.3,21.97 19.94,22.61 19.94,23.44 22.23,25.73 22.23,29.72 24.51,32 24.51,41.78 24.64,41.91 24.64,42.16 v1(24.51,42.29)
VREFP: length 5.9
  TOP w0.165: v1(51.18,46.99) 52.32,46.99 52.46,47.13 U28.10 J32.10
  BOTTOM w0.165: v1(51.18,46.99) C468.1 R65.2
XTAL1: length 14.6
  TOP w0.165: U16.B1 8.64,31.77 8.64,27.92 6.95,26.24 C79.1 Y1.2
XTAL2: length 15.6
  TOP w0.165: Y1.1 C80.1 10.72,26.29 9.14,27.86 9.14,30.76 11.44,33.05 U16.C1
XTAL32K_N: length 11.7
  TOP w0.165: C465.1 74.96,44.14 74.96,44.14 Y3.1 73.8,43.39 72.06,45.13 U28.35 J32.35
XTAL32K_P: length 13.8
  TOP w0.165: C464.1 74.96,40.13 74.96,40.14 Y3.2 73.28,40.89 72.9,41.27 72.9,43.43 71.7,44.63 U28.34 J32.34
XTAL32M_N: length 12.9
  TOP w0.165: J32.19 U28.19 57.19,40.81 54.43,38.05 54.43,33.47 53.43,32.47 Y2.1 52.43,32.47 52.42,32.47 C463.1
XTAL32M_P: length 10.5
  TOP w0.165: J32.20 U28.20 57.69,40.8 55.53,38.64 Y2.3 56.43,34.17 56.44,34.18 C462.1
N00831: length 15.1
  TOP w0.508: 5.34,64.02 J1.6 4.53,64.73 ; 5.95,56.78 L2.1 6.55,56.28 ; 1.53,56.7 J1.9 ; J1.8 1.53,66.49 ; 4.53,58.45 J1.7
  BOTTOM w0.508: J1.9 2.79,57.94 ; J1.9 1.53,59 ; J1.9 1.53,57.16 ; J1.8 2.79,65.24 ; J1.8 1.53,66.02 ; J1.8 1.53,64.19 ; 4.53,58.45 J1.7 3.71,59.17 ; 3.71,64.02 J1.6 4.53,64.73
N00949: length 14
  TOP w0.165: v2(11.3,64.14) 11.29,64.15 L1.1
  TOP w0.381: J1.1 5.62,62.89 7.06,64.34 C1.1 9.56,64.34 9.75,64.15 L1.1
  BOTTOM w0.165: U2.6 6.28,62.82 7.59,64.14 v2(11.3,64.14)
N00991: length 7.4
  TOP w0.14: J1.2 5.07,62.24 5.31,62 8.31,62 v1(8.74,62.43) 9.06,62.1 9.7,62.1 R1.1
  BOTTOM w0.14: U2.1 8.48,62.17 v1(8.74,62.43)
N01033: length 7.3
  TOP w0.14: R2.1 9.68,61.82 9.16,61.82 v1(8.74,61.41) 8.42,61.72 5.3,61.72 5.17,61.59 J1.3
  BOTTOM w0.14: v1(8.74,61.41) 8.47,61.67 U2.2
N01077: length 9.9
  TOP w0.165: J1.4 7.23,60.94 v1(7.8,60.38) 8.36,60.38 8.48,60.25 R3.1 11.6,59.48 11.6,59.48 TP5.1
  BOTTOM w0.165: U2.3 7.8,61.17 v1(7.8,60.38)
N10980: length 6.9
  TOP w0.102: U16.E5 v1(12.64,36.57) ; U16.E4 v1(12.64,35.77) ; U16.F4 v1(14.23,35.77)
  TOP w0.254: 20.11,35.71 L10.2 20.8,35.16 ; 20.8,33.98 C73.1 ; C73.1 20.8,35 ; C73.1 20.29,34.49 ; C74.1 20.8,33.81 ; C74.1 20.8,32.79 ; C74.1 20.29,33.3 ; 20.41,32.16 C75.1 20.84,32.65
  vias: v1(18.92,35.26) v1(18.92,34.52) v1(18.92,33.78) v1(19.74,35.23) v1(19.74,34.49) v1(19.74,33.76) v1(19.76,32.94)
N11774: length 2.7
  TOP w0.165: R103.2 U16.A10
N11936: length 3.8
  TOP w0.165: R107.1 v1(19.05,40.39) ; U16.J9 v1(16.63,40.57)
  BOTTOM w0.165: v1(19.05,40.39) 18.67,40.39 18.49,40.57 v1(16.63,40.57)
N11954: length 6.9
  TOP w0.102: U16.E3 13.44,34.97 13.44,33.27
  TOP w0.165: 13.44,33.27 16.28,30.43 R94.1
N11988: length 6.5
  TOP w0.102: U16.F9 v1(14.23,40.57)
  TOP w0.165: R108.1 v1(19.05,41.53)
  BOTTOM w0.165: v1(14.23,40.57) 15.2,41.53 v1(19.05,41.53)
N12006: length 5.5
  TOP w0.165: U16.F1 v1(15.02,32.59) 17.35,30.26 R93.1
N12034: length 6.4
  TOP w0.102: U16.F8 v1(14.23,39.77)
  TOP w0.165: R109.1 v1(19.05,39.24)
  BOTTOM w0.165: v1(14.23,39.77) 14.52,39.48 14.52,39.48 14.76,39.24 v1(19.05,39.24)
N12048: length 7.5
  TOP w0.102: U16.F3 v1(14.23,34.97)
  TOP w0.165: R95.1 18.41,29.97 v1(17.65,30.73)
  BOTTOM w0.165: v1(17.65,30.73) 14.76,33.63 14.76,34.45 v1(14.23,34.97)
N12060: length 4.6
  TOP w0.102: 11.84,41.3 11.84,40.57 U16.C9
  TOP w0.165: R110.1 12.57,43.54 12.57,42.93 11.84,42.19 11.84,41.3
N12096: length 9.9
  TOP w0.165: U16.D2 U16.D1 12.24,32.05 10.77,30.58 C77.1 C76.1 11.87,29.74 C78.1 13.94,29.74 R152.2 R151.2
N12268: length 2.8
  TOP w0.165: U16.A6 v1(8.6,37.77) 8.31,37.77 8.23,37.85 R96.2
N12370: length 2.8
  TOP w0.165: U16.A4 v1(8.88,36.17) 8.23,36.17 8.13,36.07 R97.2
N12878: length 1.3
  TOP w0.165: R106.2 D8.A
N26173: length 27.9
  TOP w0.165: R104.1 5.08,35.18 0.97,31.06 0.97,14.63 3.25,12.34 J16.9
N35294: length 1.8
  TOP w0.165: R111.1 39.37,65.64 39.68,65.33 U17.7
N35350: length 1.8
  TOP w0.165: R112.1 40.77,65.77 40.33,65.34 U17.6
N35394: length 1.4
  TOP w0.165: U17.5 41.71,64.65 41.72,64.64 R113.1
N35580: length 3.7
  TOP w0.165: D9.C 43.66,83.24 42.67,82.25 JP8.3
N35730: length 2.6
  TOP w0.165: U19.4 29.2,86.37 29.54,86.03 R116.2 R118.1
N36212: length 3.6
  TOP w0.165: U20.4 29.86,80.87 R122.2 30.15,80.58 R123.1 v1(29.11,79.73)
N36294: length 15.4
  TOP w0.165: R119.1 R117.1 41.87,76.2 v1(41.87,76.2) 42.26,76.2 42.5,75.96 U18.2
  BOTTOM w0.165: JP7.1 42.93,82.17 41.87,81.12 v1(41.87,76.2)
N36440: length 2.3
  TOP w0.165: JP7.2 49.97,84.71 50.1,84.84 R121.1
N36658: length 3.7
  TOP w0.165: U21.4 29.75,74.04 R126.2 R127.1 v1(29.14,72.75)
N37764: length 1.6
  TOP w0.165: U19.5 29.63,87.02 29.65,87.05 R120.1
N44150: length 2.8
  TOP w0.165: U18.1 42.67,76.36 41.94,77.09 R114.1
N59397: length 2.2
  TOP w0.165: U22.6 23.38,46.16 23.22,46 v1(22.85,46) R132.1
N60020: length 2.2
  TOP w0.165: R133.1 28.18,46.02 28.04,46.16 v1(27.59,46.16) U22.11
N63149: length 2.8
  TOP w0.165: J18.1 24.22,6.34 24.26,6.37 R139.2
N63153: length 3
  TOP w0.165: R141.2 R136.1 R137.1
N63221: length 2.8
  TOP w0.165: R138.2 21.69,6.34 21.68,6.34 J18.3
N63225: length 5.8
  TOP w0.165: R142.1 20.45,4.03 J18.4
N63293: length 2.8
  TOP w0.165: R140.2 19.15,6.34 19.14,6.34 J18.5
N63337: length 2.8
  TOP w0.165: R143.2 16.61,6.34 16.6,6.34 J18.7
N67918: length 2.1
  TOP w0.165: v1(27.43,42.08) R135.1 U23.4
N70850: length 19.4
  TOP w0.165: R150.1 C98.1 R147.2 ; R147.2 98.06,46.35 100.68,48.97 102.46,48.97 103.05,48.38 SW4.1 SW4.2 ; R147.2 97.41,47.37 96.65,48.13 94.74,48.13 JS3.1
N73960: length 5.8
  TOP w0.165: R144.1 17.91,4.03 J18.6
N73966: length 5.8
  TOP w0.165: R145.1 15.37,4.03 J18.8
N74033: length 5.8
  TOP w0.165: J18.2 22.99,4.03 R141.1
N75462: length 8.4
  TOP w0.165: v1(27.31,22.48) R23.1 R20.2
  BOTTOM w0.165: J3.1 27.31,25.41 v1(27.31,22.48)
N75944: length 10.4
  TOP w0.165: U11.9 22.99,28.05 22.99,28.05 22.99,29.21 25.1,31.32 R28.1 27.76,31.32 29.34,32.89
N76496: length 3.9
  TOP w0.165: J3.2 28.52,25.71 R25.1
N76500: length 2.1
  TOP w0.165: v1(26.57,24.69) 26.56,24.69 R25.2 U11.4
N76504: length 2.4
  TOP w0.165: U11.3 25.11,24.19 R23.2 v1(26.62,23.49)
N76612: length 1.8
  TOP w0.165: R24.1 20.84,24.19 U11.14
N76618: length 1.6
  TOP w0.165: R26.1 U11.13
N76712: length 2.5
  TOP w0.165: R130.1 v1(27.93,47.66) U22.14
N76718: length 2.2
  TOP w0.165: U22.13 R131.1
N79087: length 14.5
  TOP w0.165: SW1.2 SW1.1 103.05,15.08 102.26,15.88 99.06,15.88 v1(97.41,14.22) R43.2 C32.1 R46.1
N79544: length 13.7
  TOP w0.165: SW2.2 SW2.1 103.05,37.1 v1(102.22,37.94) 100.1,37.94 R44.2 C33.1 R48.1
N80467: length 14.3
  TOP w0.165: R47.1 C34.1 R45.2 97.28,25.03 99.12,26.86 v1(102.17,26.86) 102.19,26.86 103.05,26.01 SW3.1 SW3.2
N84474: length 3.1
  TOP w0.165: v1(96.62,80.16) R30.2 97.98,79.79 97.98,79.33 98.41,78.91 Q4.6 98.41,78.46 Q4.7
N84482: length 3.2
  TOP w0.165: R30.1 97.08,81.71 D4.3
N84508: length 3.3
  TOP w0.165: Q4.3 99.11,78.31 Q4.8 100,78.38 100.28,78.66 R31.2
N84516: length 3.2
  TOP w0.165: R31.1 100.79,81.69 D4.4
N84524: length 9.2
  TOP w0.165: R38.1 100.2,90.3 100.79,89.71 D4.1
N84614: length 3.2
  TOP w0.165: R160.1 Q4.2 ; R160.1 R161.2 ; R160.1 v1(99.74,76.61)
N84618: length 2.3
  TOP w0.165: Q4.5 98.76,79.2 98.5,79.45 R162.2 R163.1
N84662: length 1.1
  TOP w0.165: R37.2 D5.A
N84682: length 2.9
  TOP w0.165: v1(93.4,91.29) R38.2 92.84,90.3 92.55,90.01 Q5.6 91.69,90.01 Q5.7
N84732: length 3.4
  TOP w0.165: v1(90.25,87.64) D5.C 91.24,88.27 91.62,88.65 Q5.8 91.54,89.31 Q5.3
N84806: length 2.6
  TOP w0.165: R165.1 R164.2 Q5.2
N105040: length 3
  TOP w0.165: U9.8 53.63,95.59 53.58,95.63 R29.1 v2(54.99,96.21)
N105919: length 33
  TOP w0.165: J19.M1 34.32,107.34 51.43,107.34 J19.M2 59.24,103.4 59.28,103.44 L7.1
N108963: length 16.2
  TOP w0.165: TP10.1 101.8,74.68 102.01,74.88 103.22,74.88 103.37,74.73 R32.2 103.8,73.91 104.53,73.19 104.53,66.74 104.1,66.31 v1(103.89,66.31) U12.9
N108967: length 9.8
  TOP w0.165: U12.11 103.77,67.31 v1(104.02,67.56) 104.02,71.11 R36.2 103.38,72.31 103.37,72.31 R33.2
N109097: length 9.9
  TOP w0.165: R39.1 R34.2 v1(100.95,60.45) 98.93,60.45 98.55,60.82 U12.7
N109101: length 10.5
  TOP w0.165: R35.2 R40.1 103.45,61.47 v1(103.84,61.86) ; U12.10 v1(103,66.81)
  BOTTOM w0.165: v1(103,66.81) 103,66.41 103.84,65.58 v1(103.84,61.86)
N109113: length 4.3
  TOP w0.165: U12.8 99.05,63.25 99.44,62.86 v1(100.43,62.86)
N109175: length 3.4
  TOP w0.165: R41.1 97.41,71.06 98.05,70.42 U12.16
N109231: length 6.1
  TOP w0.165: U12.2 95.53,67.81 94.61,68.73 C31.1
N110947: length 1.5
  TOP w0.165: R42.1 92.88,89.41 92.62,89.66 Q5.5
N112208: length 3.3
  TOP w0.165: U9.1 47.73,94.61 v1(46.83,95.51) 46.48,95.87 U26.4
N112220: length 3
  TOP w0.165: U9.4 47.22,90.8 47.21,90.79 U25.4
N115095: length 4.5
  TOP w0.165: C55.1 R153.2 75.52,21.63 J7.7
N115099: length 5
  TOP w0.165: C56.1 45.42,21.62 R154.2 J8.7
N115914: length 2.8
  TOP w0.165: J10.7 R62.2
N116004: length 2.8
  TOP w0.165: J10.19 R60.2
N116129: length 3.2
  TOP w0.165: R61.1 J9.6
N339341: length 2.2
  TOP w0.165: R158.2 29.08,36.63 29.34,36.37 JP12.1
N346834: length 3.7
  TOP w0.165: R111.2 37.72,66.29 36.47,67.54 JP13.1
N346895: length 3.4
  TOP w0.165: JP14.2 41.78,66.93 R112.2
N346946: length 2.8
  TOP w0.165: R118.2 32.77,85.12 32.92,85.27 JP15.1
N347023: length 3
  TOP w0.165: R123.2 31.74,79.16 JP16.1
N347072: length 2.7
  TOP w0.165: R127.2 JP17.1
N348380: length 2.9
  TOP w0.165: R159.1 43.69,90.43 44.7,91.44 U25.5
N350950: length 2.2
  TOP w0.165: U26.5 v1(46.51,96.52) 46.91,96.52 46.94,96.54 R19.2
N1378690: length 3.2
  TOP w0.165: R27.2 C25.1 R21.2
N1379290: length 2.7
  TOP w0.165: JP23.1 R21.1
N1379309: length 2.7
  TOP w0.165: JP24.1 R27.1

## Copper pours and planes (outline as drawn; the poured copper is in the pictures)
GND on TOP (solid shape): 62.85,39.63 62.69,39.54 62.64,39.57 61.53,40.68 61.53,41.25 62.85,41.25
GND on TOP (solid shape): 24.74,44.65 25.19,44.65 25.19,44.07 25.2,43.98 25.1,43.86 25.07,43.85 24.85,43.8 24.69,43.65 24.61,43.63 24.59,43.63 24.56,43.64 24.54,43.64 24.51,43.63 24.43,43.65 24.39,43.7 24.39,45.38 24.6,45.38 24.6,45.71 24.74,45.71
GND on TOP (solid shape): 4.66,37.6 4.67,37.58 4.86,37.4 5.11,37.34 5.61,37.34 5.71,37.18 5.69,37.15 5.66,37.06 5.65,36.96 5.66,36.86 5.69,36.76 5.71,36.73 5.61,36.58 5.11,36.58 4.75,36.43 4.6,36.07 4.66,35.82 4.84,35.64 4.86,35.62 4.88,35.45 4.84,35.42 1.08,31.65 1,31.69 1,34.13 4.49,37.62
GND on TOP (solid shape): 49.37,76.12 49.46,76 49.58,75.91 49.58,75.73 49.27,75.18 49.58,74.64 49.58,74.46 49.36,74.23 49.27,73.91 49.28,73.83 49.14,73.72 49.07,73.74 49.02,73.74 45.48,73.74 45.31,73.91 45.31,74.55 45.29,74.67 45.22,74.77 45.2,74.79 45.2,74.93 45.61,74.93 45.61,75.62 46.36,75.62 46.42,75.61 47.25,75.61 47.32,75.6 47.37,75.59 47.43,75.6 47.49,75.61 48.01,75.61 48.14,75.64 48.25,75.71 48.65,76.12
GND on TOP (solid shape): 46.79,79.6 46.8,79.59 46.86,79.5 46.95,79.44 46.96,79.43 48.64,77.75 48.59,77.57 48.56,77.56 48.42,77.5 48.32,77.38 48.32,77.37 47.68,76.73 47.3,76.73 47.2,76.87 47.21,76.9 47.24,76.99 47.24,77.09 47.17,77.36 46.96,77.55 46.96,77.57 46.97,77.6 46.96,77.62 46.95,77.65 46.98,77.73 47.13,77.89 47.18,78.11 46.74,78.55 46.29,78.11 46.34,77.89 46.49,77.73 46.52,77.65 46.5,77.6 45.91,77.6 45.62,77.89 45.5,77.97 45.35,78 44.67,78 44.62,78 44.51,78.1 44.51,78.49 44.52,78.54 44.53,78.6 44.68,78.75 45.46,78.75 45.51,78.75 45.57,78.77 45.97,78.77 45.97,80.05 46.35,80.05
